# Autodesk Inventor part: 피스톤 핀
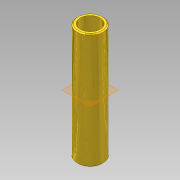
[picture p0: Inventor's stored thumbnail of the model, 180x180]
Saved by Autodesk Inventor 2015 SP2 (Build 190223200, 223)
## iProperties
Manager: KYOUNG IL JANG
Company: 한국ATC센터
Created: 2012-10
Part Number: 피스톤 핀
Document SubType Name: Modeling
Density: 1 g/cm^3
Checked By: KYOUNG IL JANG
Vendor: CBT Solutions
Designer: KYOUNG IL JANG
Material: 일반
Appearance: _시험_금속성 금색
Author: KYOUNG IL JANG
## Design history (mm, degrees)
sketch "스케치1"
  geometry: C1 r 6.5 at (0, 0); C2 r 5 at (0, 0); 1 further point
  constraints: 2 centre point, 2 coincident
  dimensions: "d0" = 13 diameter of C1; "d1" = 1.5 radial gap between concentric circles of C1 C2
extrude "돌출1" new body sketch "스케치1" stored distance "d2" = 58; taper "d3" = 0 deg
chamfer "모따기1" distance "d4" = 0.5; stored, may be unused: second distance "d5" = 2, angle "d6" = 45 deg
node "솔리드1"
